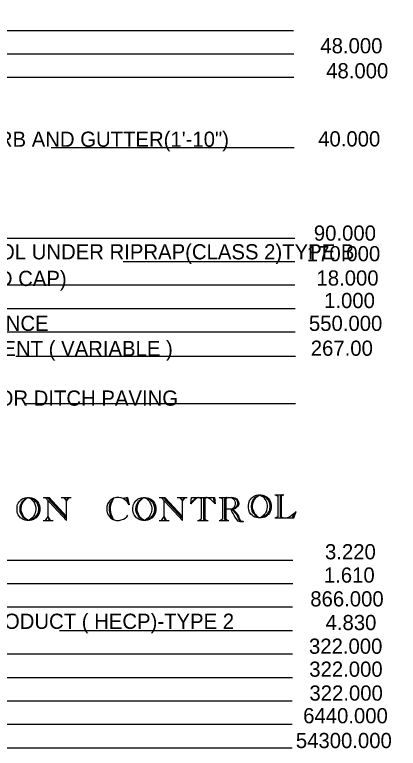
# Model space of a CAD drawing. Extents: x -13615 to 47191, y -1934 to 4415.
# Drawn here: x -11541 to -11338.5, y 1111.4 to 1498.5 of the extents above; entities that cross this region are included whole.
import ezdxf

# ---------------------------------------------------------------- set-up
doc = ezdxf.new("R2010")
doc.units = 0
doc.layers.add('Default', color=7, linetype='Continuous')

msp = doc.modelspace()

# ---------------------------------------------------------------- linework, layer by layer
at = {"layer": 'Default'}
for p, q in [((-11654.4, 1490.25), (-11428.18, 1490.25)), ((-11428.18, 1490.25), (-11419.65, 1490.25)), ((-11419.65, 1490.25), (-11407.18, 1490.25)), ((-11407.18, 1490.25), (-11399.27, 1490.25)), ((-11399.27, 1490.25), (-11393.78, 1490.25)), ((-11649.58, 1477.88), (-11428.19, 1477.88)), ((-11428.19, 1477.88), (-11420.03, 1477.88)), ((-11420.03, 1477.88), (-11406.95, 1477.88)), ((-11406.95, 1477.88), (-11399.14, 1477.88)), ((-11399.14, 1477.88), (-11393.71, 1477.88)), ((-11650.51, 1465.5), (-11428.21, 1465.5)), ((-11428.21, 1465.5), (-11420.41, 1465.5)), ((-11420.41, 1465.5), (-11406.71, 1465.5)), ((-11406.71, 1465.5), (-11399.02, 1465.5)), ((-11399.02, 1465.5), (-11393.64, 1465.5)), ((-11521.75, 1428.38), (-11428.26, 1428.38)), ((-11428.26, 1428.38), (-11421.56, 1428.38)), ((-11421.56, 1428.38), (-11406.01, 1428.38)), ((-11406.01, 1428.38), (-11398.64, 1428.38)), ((-11398.64, 1428.38), (-11393.42, 1428.38)), ((-11667.77, 1380.65), (-11428.31, 1380.65)), ((-11428.31, 1380.65), (-11422.71, 1380.65)), ((-11422.71, 1380.65), (-11415.63, 1380.65)), ((-11415.63, 1380.65), (-11405.31, 1380.65)), ((-11405.31, 1380.65), (-11398.25, 1380.65)), ((-11398.25, 1380.65), (-11393.19, 1380.65)), ((-11483.68, 1368.27), (-11428.33, 1368.27)), ((-11428.33, 1368.27), (-11423.09, 1368.27)), ((-11423.09, 1368.27), (-11417.44, 1368.27)), ((-11417.44, 1368.27), (-11405.08, 1368.27)), ((-11405.08, 1368.27), (-11398.13, 1368.27)), ((-11398.13, 1368.27), (-11393.12, 1368.27)), ((-11576.84, 1355.9), (-11428.35, 1355.9)), ((-11428.35, 1355.9), (-11423.47, 1355.9)), ((-11423.47, 1355.9), (-11419.24, 1355.9)), ((-11419.24, 1355.9), (-11404.84, 1355.9)), ((-11404.84, 1355.9), (-11398, 1355.9)), ((-11398, 1355.9), (-11393.05, 1355.9)), ((-11659.64, 1343.52), (-11428.37, 1343.52)), ((-11428.37, 1343.52), (-11423.86, 1343.52)), ((-11423.86, 1343.52), (-11421.05, 1343.52)), ((-11421.05, 1343.52), (-11404.61, 1343.52)), ((-11404.61, 1343.52), (-11397.87, 1343.52)), ((-11397.87, 1343.52), (-11392.97, 1343.52)), ((-11586.13, 1331.15), (-11428.38, 1331.15)), ((-11428.38, 1331.15), (-11424.24, 1331.15)), ((-11424.24, 1331.15), (-11422.85, 1331.15)), ((-11422.85, 1331.15), (-11404.37, 1331.15)), ((-11404.37, 1331.15), (-11397.75, 1331.15)), ((-11397.75, 1331.15), (-11392.9, 1331.15)), ((-11540.39, 1318.37), (-11392.79, 1318.37)), ((-11536.07, 1293.34), (-11392.79, 1293.34)), ((-11658.4, 1210.74), (-11394.23, 1210.74)), ((-11658.4, 1198.37), (-11394.28, 1198.37)), ((-11693.42, 1185.99), (-11394.32, 1185.99)), ((-11517.36, 1173.62), (-11394.36, 1173.62)), ((-11642.48, 1161.24), (-11394.4, 1161.24)), ((-11612.41, 1148.87), (-11394.44, 1148.87)), ((-11652.03, 1136.49), (-11394.48, 1136.49)), ((-11612.41, 1124.12), (-11394.53, 1124.12)), ((-11654.15, 1111.74), (-11394.57, 1111.74))]:
    msp.add_line(p, q, dxfattribs=at)
for points in [[(-11537.28, 1232.6), (-11537.91, 1233.08), (-11538.55, 1233.71), (-11539.18, 1234.65), (-11539.33, 1234.97), (-11539.49, 1235.44), (-11539.65, 1235.92), (-11539.81, 1237.02), (-11539.81, 1238.28), (-11539.65, 1239.39), (-11539.49, 1240.02), (-11539.18, 1240.81), (-11538.7, 1241.44), (-11538.23, 1242.07), (-11537.91, 1242.39), (-11537.28, 1242.86), (-11536.81, 1243.17), (-11536.02, 1243.49), (-11535.55, 1243.65), (-11534.44, 1243.81), (-11533.81, 1243.81), (-11532.71, 1243.65), (-11532.23, 1243.49), (-11531.45, 1243.17), (-11530.97, 1242.86), (-11530.5, 1242.54), (-11529.71, 1241.75), (-11529.08, 1240.97), (-11528.76, 1240.49), (-11528.61, 1240.18), (-11528.45, 1239.7), (-11528.29, 1239.07), (-11528.13, 1238.13), (-11528.13, 1237.65), (-11528.29, 1236.39), (-11528.45, 1235.76), (-11528.61, 1235.44), (-11528.76, 1234.97), (-11529.08, 1234.5), (-11529.39, 1234.02), (-11530.03, 1233.39), (-11530.5, 1232.92), (-11530.97, 1232.6), (-11531.76, 1232.13), (-11532.23, 1231.97), (-11532.71, 1231.81), (-11533.81, 1231.66), (-11534.29, 1231.81), (-11534.6, 1231.97), (-11535.23, 1232.29), (-11535.86, 1232.76), (-11536.49, 1233.39), (-11537.13, 1234.18), (-11537.44, 1234.65), (-11537.76, 1235.29), (-11538.07, 1236.23), (-11538.23, 1237.34), (-11538.23, 1237.97), (-11538.07, 1239.07), (-11537.91, 1239.7), (-11537.76, 1240.18), (-11537.6, 1240.49), (-11537.44, 1240.81), (-11536.81, 1241.75), (-11536.18, 1242.39), (-11535.86, 1242.7), (-11535.39, 1243.02), (-11534.92, 1243.33), (-11534.6, 1243.49), (-11533.81, 1243.81), (-11532.55, 1243.49), (-11532.08, 1243.33), (-11531.76, 1243.17), (-11531.29, 1242.86), (-11530.81, 1242.54)], [(-11530.81, 1242.54), (-11530.34, 1242.07), (-11529.87, 1241.6), (-11529.55, 1241.28), (-11529.39, 1240.97), (-11528.92, 1240.02), (-11528.61, 1239.07), (-11528.45, 1238.13), (-11528.45, 1237.49), (-11528.61, 1236.39), (-11528.76, 1235.76), (-11529.08, 1234.97), (-11529.39, 1234.5), (-11529.71, 1234.02), (-11530.81, 1232.92), (-11531.45, 1232.45), (-11532.08, 1232.13), (-11532.55, 1231.97), (-11533.81, 1231.66), (-11534.76, 1232.13), (-11535.39, 1232.6), (-11536.18, 1233.23), (-11536.81, 1234.02), (-11537.28, 1234.97), (-11537.76, 1236.23), (-11537.91, 1237.34), (-11537.91, 1237.97), (-11537.76, 1239.23), (-11537.6, 1239.7), (-11537.28, 1240.49), (-11536.97, 1241.12), (-11536.65, 1241.6), (-11535.86, 1242.54), (-11535.23, 1243.02), (-11534.76, 1243.33), (-11533.81, 1243.81), (-11533.5, 1243.65), (-11532.71, 1243.17), (-11532.08, 1242.7), (-11531.76, 1242.39), (-11531.13, 1241.6), (-11530.66, 1240.81), (-11530.34, 1240.18), (-11530.03, 1239.23), (-11529.87, 1238.28), (-11529.87, 1237.49), (-11530.03, 1236.39), (-11530.18, 1235.76), (-11530.34, 1235.29), (-11530.66, 1234.65), (-11530.97, 1234.02), (-11531.45, 1233.39), (-11531.92, 1232.92), (-11532.71, 1232.29), (-11533.18, 1231.97), (-11533.81, 1231.66), (-11534.6, 1232.13), (-11535.07, 1232.45), (-11535.55, 1232.92), (-11536.18, 1233.55), (-11536.49, 1234.02), (-11536.97, 1234.97), (-11537.44, 1236.23), (-11537.6, 1237.34), (-11537.6, 1237.97), (-11537.44, 1239.23), (-11537.28, 1239.86), (-11536.97, 1240.65), (-11536.81, 1240.97), (-11536.49, 1241.44), (-11536.18, 1241.91), (-11535.71, 1242.39), (-11535.39, 1242.7), (-11534.6, 1243.33), (-11533.81, 1243.81), (-11533.18, 1243.81), (-11532.23, 1243.65), (-11531.6, 1243.49), (-11530.66, 1243.02), (-11529.87, 1242.54), (-11529.24, 1241.91), (-11528.76, 1241.28), (-11528.45, 1240.81), (-11528.13, 1240.02), (-11527.97, 1239.55), (-11527.82, 1238.28), (-11527.82, 1237.02), (-11527.97, 1235.92), (-11528.13, 1235.44), (-11528.29, 1234.97), (-11528.76, 1234.18), (-11529.08, 1233.71), (-11529.71, 1233.08), (-11530.34, 1232.6), (-11531.13, 1232.13), (-11532.08, 1231.81), (-11533.02, 1231.66), (-11534.6, 1231.66), (-11535.55, 1231.81), (-11536.49, 1232.13), (-11537.28, 1232.6)], [(-11525.92, 1243.81), (-11522.92, 1243.81), (-11513.62, 1233.71)], [(-11524.98, 1243.81), (-11513.62, 1231.66), (-11513.62, 1241.75), (-11512.2, 1243.81)], [(-11523.87, 1243.81), (-11513.62, 1232.76)], [(-11523.4, 1243.81), (-11513.62, 1233.39)], [(-11516.46, 1243.81), (-11511.25, 1243.81)], [(-11515.04, 1243.81), (-11513.62, 1241.75), (-11512.98, 1243.81)], [(-11513.62, 1241.75), (-11512.67, 1243.81)], [(-11483.79, 1243.17), (-11481.43, 1243.81), (-11480.64, 1239.86), (-11481.74, 1241.6), (-11482.37, 1242.23), (-11483.79, 1243.17), (-11484.9, 1243.65), (-11486, 1243.81), (-11487.26, 1243.81), (-11488.05, 1243.65), (-11488.84, 1243.33), (-11489.95, 1242.7), (-11490.42, 1242.39), (-11491.05, 1241.75), (-11491.84, 1240.65), (-11492.47, 1239.07), (-11492.47, 1236.71), (-11492, 1235.13), (-11491.05, 1233.71), (-11490.42, 1233.08), (-11489, 1232.13), (-11488.05, 1231.81), (-11487.26, 1231.66), (-11485.84, 1231.66), (-11484.74, 1231.97), (-11483.64, 1232.29), (-11482.69, 1232.92), (-11481.9, 1233.55), (-11481.27, 1234.5)], [(-11488.84, 1243.33), (-11489.79, 1241.44), (-11490.26, 1240.18), (-11490.58, 1238.6), (-11490.58, 1237.02), (-11490.26, 1235.13), (-11489.95, 1234.5), (-11489.32, 1233.08), (-11489.16, 1232.76), (-11488.53, 1231.97), (-11489.47, 1232.92), (-11490.11, 1234.02), (-11490.58, 1235.13), (-11490.89, 1236.71), (-11490.89, 1238.44), (-11490.58, 1240.02), (-11490.26, 1240.81), (-11489.79, 1241.91), (-11488.84, 1243.33), (-11489.47, 1242.54), (-11489.95, 1241.91), (-11490.26, 1241.28), (-11490.74, 1240.65), (-11491.21, 1239.07), (-11491.21, 1236.71), (-11490.58, 1234.65), (-11490.42, 1234.18), (-11490.11, 1233.55), (-11489.63, 1232.92), (-11489.32, 1232.6), (-11488.68, 1232.13)], [(-11480.64, 1239.86), (-11481.43, 1243.81), (-11483.79, 1243.17)], [(-11482.06, 1243.65), (-11481.74, 1241.6)], [(-11481.74, 1243.65), (-11481.27, 1240.81)], [(-11476.06, 1232.6), (-11476.69, 1233.08), (-11477.32, 1233.71), (-11477.96, 1234.65), (-11478.11, 1234.97), (-11478.27, 1235.44), (-11478.43, 1235.92), (-11478.59, 1237.02), (-11478.59, 1238.28), (-11478.43, 1239.39), (-11478.27, 1240.02), (-11477.96, 1240.81), (-11477.48, 1241.44), (-11477.01, 1242.07), (-11476.69, 1242.39), (-11476.06, 1242.86), (-11475.59, 1243.17), (-11474.8, 1243.49), (-11474.33, 1243.65), (-11473.22, 1243.81), (-11472.59, 1243.81), (-11471.49, 1243.65), (-11471.01, 1243.49), (-11470.22, 1243.17), (-11469.75, 1242.86), (-11469.28, 1242.54), (-11468.49, 1241.75), (-11467.86, 1240.97), (-11467.54, 1240.49), (-11467.38, 1240.18), (-11467.23, 1239.7), (-11467.07, 1239.07), (-11466.91, 1238.13), (-11466.91, 1237.65), (-11467.07, 1236.39), (-11467.23, 1235.76), (-11467.38, 1235.44), (-11467.54, 1234.97), (-11467.86, 1234.5), (-11468.17, 1234.02), (-11468.8, 1233.39), (-11469.28, 1232.92), (-11469.75, 1232.6), (-11470.54, 1232.13), (-11471.01, 1231.97), (-11471.49, 1231.81), (-11472.59, 1231.66), (-11473.06, 1231.81), (-11473.38, 1231.97), (-11474.01, 1232.29), (-11474.64, 1232.76), (-11475.27, 1233.39), (-11475.9, 1234.18), (-11476.22, 1234.65), (-11476.54, 1235.29), (-11476.85, 1236.23), (-11477.01, 1237.34), (-11477.01, 1237.97), (-11476.85, 1239.07), (-11476.69, 1239.7), (-11476.54, 1240.18), (-11476.38, 1240.49), (-11476.22, 1240.81), (-11475.59, 1241.75), (-11474.96, 1242.39), (-11474.64, 1242.7), (-11474.17, 1243.02), (-11473.7, 1243.33), (-11473.38, 1243.49), (-11472.59, 1243.81), (-11471.33, 1243.49), (-11470.85, 1243.33), (-11470.54, 1243.17), (-11470.07, 1242.86), (-11469.59, 1242.54)], [(-11469.59, 1242.54), (-11469.12, 1242.07), (-11468.65, 1241.6), (-11468.33, 1241.28), (-11468.17, 1240.97), (-11467.7, 1240.02), (-11467.38, 1239.07), (-11467.23, 1238.13), (-11467.23, 1237.49), (-11467.38, 1236.39), (-11467.54, 1235.76), (-11467.86, 1234.97), (-11468.17, 1234.5), (-11468.49, 1234.02), (-11469.59, 1232.92), (-11470.22, 1232.45), (-11470.85, 1232.13), (-11471.33, 1231.97), (-11472.59, 1231.66), (-11473.54, 1232.13), (-11474.17, 1232.6), (-11474.96, 1233.23), (-11475.59, 1234.02), (-11476.06, 1234.97), (-11476.54, 1236.23), (-11476.69, 1237.34), (-11476.69, 1237.97), (-11476.54, 1239.23), (-11476.38, 1239.7), (-11476.06, 1240.49), (-11475.75, 1241.12), (-11475.43, 1241.6), (-11474.64, 1242.54), (-11474.01, 1243.02), (-11473.54, 1243.33), (-11472.59, 1243.81), (-11472.28, 1243.65), (-11471.49, 1243.17), (-11470.85, 1242.7), (-11470.54, 1242.39), (-11469.91, 1241.6), (-11469.43, 1240.81), (-11469.12, 1240.18), (-11468.8, 1239.23), (-11468.65, 1238.28), (-11468.65, 1237.49), (-11468.8, 1236.39), (-11468.96, 1235.76), (-11469.12, 1235.29), (-11469.43, 1234.65), (-11469.75, 1234.02), (-11470.22, 1233.39), (-11470.7, 1232.92), (-11471.49, 1232.29), (-11471.96, 1231.97), (-11472.59, 1231.66), (-11473.38, 1232.13), (-11473.85, 1232.45), (-11474.33, 1232.92), (-11474.96, 1233.55), (-11475.27, 1234.02), (-11475.75, 1234.97), (-11476.22, 1236.23), (-11476.38, 1237.34), (-11476.38, 1237.97), (-11476.22, 1239.23), (-11476.06, 1239.86), (-11475.75, 1240.65), (-11475.59, 1240.97), (-11475.27, 1241.44), (-11474.96, 1241.91), (-11474.48, 1242.39), (-11474.17, 1242.7), (-11473.38, 1243.33), (-11472.59, 1243.81), (-11471.96, 1243.81), (-11471.01, 1243.65), (-11470.38, 1243.49), (-11469.43, 1243.02), (-11468.65, 1242.54), (-11468.01, 1241.91), (-11467.54, 1241.28), (-11467.23, 1240.81), (-11466.91, 1240.02), (-11466.75, 1239.55), (-11466.59, 1238.28), (-11466.59, 1237.02), (-11466.75, 1235.92), (-11466.91, 1235.44), (-11467.07, 1234.97), (-11467.54, 1234.18), (-11467.86, 1233.71), (-11468.49, 1233.08), (-11469.12, 1232.6), (-11469.91, 1232.13), (-11470.85, 1231.81), (-11471.8, 1231.66), (-11473.38, 1231.66), (-11474.33, 1231.81), (-11475.27, 1232.13), (-11476.06, 1232.6)], [(-11464.7, 1243.81), (-11461.7, 1243.81), (-11452.39, 1233.71)], [(-11463.75, 1243.81), (-11452.39, 1231.66), (-11452.39, 1241.75), (-11450.97, 1243.81)], [(-11462.65, 1243.81), (-11452.39, 1232.76)], [(-11462.18, 1243.81), (-11452.39, 1233.39)], [(-11455.23, 1243.81), (-11450.03, 1243.81)], [(-11453.81, 1243.81), (-11452.39, 1241.75), (-11451.76, 1243.81)], [(-11452.39, 1241.75), (-11451.45, 1243.81)], [(-11444.03, 1243.81), (-11444.5, 1243.65), (-11444.82, 1243.33), (-11445.77, 1242.7), (-11447.98, 1240.49), (-11447.66, 1243.81), (-11435.51, 1243.81), (-11435.19, 1240.49), (-11435.67, 1240.97), (-11437.56, 1242.7), (-11439.3, 1243.81)], [(-11444.35, 1243.81), (-11445.29, 1243.17), (-11445.77, 1242.86), (-11446.24, 1242.39), (-11447.03, 1241.6), (-11447.5, 1241.12), (-11447.98, 1240.49), (-11447.66, 1241.12), (-11447.19, 1241.6), (-11446.71, 1242.39), (-11445.92, 1243.02), (-11445.45, 1243.49), (-11444.66, 1243.81)], [(-11443.72, 1243.81), (-11442.61, 1243.17), (-11442.61, 1232.29), (-11443.72, 1231.66)], [(-11440.24, 1243.81), (-11441.35, 1243.17), (-11441.35, 1232.29), (-11440.24, 1231.66)], [(-11439.93, 1243.81), (-11441.03, 1243.17), (-11441.03, 1232.29), (-11439.93, 1231.66)], [(-11439.61, 1243.81), (-11440.72, 1243.17), (-11440.72, 1232.29), (-11439.61, 1231.66)], [(-11436.14, 1243.81), (-11435.83, 1241.12)], [(-11435.83, 1243.81), (-11435.51, 1240.81)], [(-11433.14, 1243.81), (-11425.73, 1243.81), (-11425.1, 1243.65), (-11423.83, 1243.02), (-11423.05, 1241.91), (-11422.73, 1240.81), (-11422.73, 1240.18), (-11423.2, 1239.07), (-11423.68, 1238.6), (-11424.47, 1237.97), (-11425.57, 1237.65), (-11425.73, 1237.65), (-11424.62, 1237.97), (-11424.31, 1238.13), (-11423.68, 1238.91), (-11423.05, 1240.33), (-11423.05, 1241.12), (-11423.52, 1242.23), (-11423.83, 1242.7), (-11424.31, 1243.17), (-11425.1, 1243.49), (-11425.57, 1243.65), (-11426.36, 1243.81), (-11425.73, 1243.65), (-11425.25, 1243.49), (-11424.78, 1243.17), (-11424.31, 1242.86), (-11423.83, 1242.39), (-11423.52, 1241.6), (-11423.36, 1241.12), (-11423.36, 1240.33), (-11423.68, 1239.23), (-11424.78, 1238.13), (-11425.25, 1237.81), (-11425.73, 1237.65), (-11429.51, 1237.65)], [(-11432.51, 1243.81), (-11431.41, 1243.02), (-11431.41, 1232.29), (-11432.51, 1231.66)], [(-11429.2, 1243.81), (-11430.3, 1243.02), (-11430.3, 1232.29), (-11429.2, 1231.66)], [(-11428.88, 1243.81), (-11429.83, 1243.02), (-11429.83, 1232.29), (-11428.88, 1231.66)], [(-11428.41, 1243.81), (-11429.51, 1243.02), (-11429.51, 1232.29), (-11428.41, 1231.66)], [(-11426.36, 1243.81), (-11425.41, 1242.86), (-11424.78, 1241.75), (-11424.62, 1241.12), (-11424.62, 1240.33), (-11424.78, 1239.55), (-11425.41, 1238.28), (-11426.36, 1237.65), (-11425.73, 1237.18), (-11424.94, 1236.71), (-11423.99, 1235.76), (-11423.68, 1235.29), (-11423.52, 1234.97), (-11423.2, 1234.5), (-11422.89, 1233.87), (-11422.73, 1233.39), (-11422.57, 1232.76), (-11422.26, 1232.29), (-11422.1, 1231.97), (-11421.63, 1231.5), (-11421.15, 1231.34), (-11420.84, 1231.18), (-11420.21, 1231.18), (-11420.84, 1230.87), (-11421.94, 1230.87), (-11422.57, 1231.03), (-11423.05, 1231.34), (-11423.68, 1232.13), (-11424.62, 1233.39), (-11425.25, 1234.18), (-11425.73, 1235.29), (-11426.2, 1236.07), (-11426.52, 1236.86), (-11426.83, 1237.65)], [(-11415.11, 1233.93), (-11415.74, 1234.4), (-11416.38, 1235.03), (-11417.01, 1235.98), (-11417.16, 1236.3), (-11417.32, 1236.77), (-11417.48, 1237.24), (-11417.64, 1238.35), (-11417.64, 1239.61), (-11417.48, 1240.71), (-11417.32, 1241.34), (-11417.01, 1242.13), (-11416.53, 1242.76), (-11416.06, 1243.4), (-11415.74, 1243.71), (-11415.11, 1244.18), (-11414.64, 1244.5), (-11413.85, 1244.82), (-11413.38, 1244.97), (-11412.27, 1245.13), (-11411.64, 1245.13), (-11410.54, 1244.97), (-11410.06, 1244.82), (-11409.28, 1244.5), (-11408.8, 1244.18), (-11408.33, 1243.87), (-11407.54, 1243.08), (-11406.91, 1242.29), (-11406.59, 1241.82), (-11406.44, 1241.5), (-11406.28, 1241.03), (-11406.12, 1240.4), (-11405.96, 1239.45), (-11405.96, 1238.98), (-11406.12, 1237.72), (-11406.28, 1237.08), (-11406.44, 1236.77), (-11406.59, 1236.3), (-11406.91, 1235.82), (-11407.22, 1235.35), (-11407.86, 1234.72), (-11408.33, 1234.24), (-11408.8, 1233.93), (-11409.59, 1233.46), (-11410.06, 1233.3), (-11410.54, 1233.14), (-11411.64, 1232.98), (-11412.12, 1233.14), (-11412.43, 1233.3), (-11413.06, 1233.61), (-11413.69, 1234.09), (-11414.32, 1234.72), (-11414.96, 1235.51), (-11415.27, 1235.98), (-11415.59, 1236.61), (-11415.9, 1237.56), (-11416.06, 1238.66), (-11416.06, 1239.29), (-11415.9, 1240.4), (-11415.74, 1241.03), (-11415.59, 1241.5), (-11415.43, 1241.82), (-11415.27, 1242.13), (-11414.64, 1243.08), (-11414.01, 1243.71), (-11413.69, 1244.03), (-11413.22, 1244.34), (-11412.75, 1244.66), (-11412.43, 1244.82), (-11411.64, 1245.13), (-11410.38, 1244.82), (-11409.91, 1244.66), (-11409.59, 1244.5), (-11409.12, 1244.18), (-11408.64, 1243.87)], [(-11408.64, 1243.87), (-11408.17, 1243.4), (-11407.7, 1242.92), (-11407.38, 1242.61), (-11407.22, 1242.29), (-11406.75, 1241.34), (-11406.44, 1240.4), (-11406.28, 1239.45), (-11406.28, 1238.82), (-11406.44, 1237.72), (-11406.59, 1237.08), (-11406.91, 1236.3), (-11407.22, 1235.82), (-11407.54, 1235.35), (-11408.64, 1234.24), (-11409.28, 1233.77), (-11409.91, 1233.46), (-11410.38, 1233.3), (-11411.64, 1232.98), (-11412.59, 1233.46), (-11413.22, 1233.93), (-11414.01, 1234.56), (-11414.64, 1235.35), (-11415.11, 1236.3), (-11415.59, 1237.56), (-11415.74, 1238.66), (-11415.74, 1239.29), (-11415.59, 1240.56), (-11415.43, 1241.03), (-11415.11, 1241.82), (-11414.8, 1242.45), (-11414.48, 1242.92), (-11413.69, 1243.87), (-11413.06, 1244.34), (-11412.59, 1244.66), (-11411.64, 1245.13), (-11411.33, 1244.97), (-11410.54, 1244.5), (-11409.91, 1244.03), (-11409.59, 1243.71), (-11408.96, 1242.92), (-11408.49, 1242.13), (-11408.17, 1241.5), (-11407.86, 1240.56), (-11407.7, 1239.61), (-11407.7, 1238.82), (-11407.86, 1237.72), (-11408.01, 1237.08), (-11408.17, 1236.61), (-11408.49, 1235.98), (-11408.8, 1235.35), (-11409.28, 1234.72), (-11409.75, 1234.24), (-11410.54, 1233.61), (-11411.01, 1233.3), (-11411.64, 1232.98), (-11412.43, 1233.46), (-11412.9, 1233.77), (-11413.38, 1234.24), (-11414.01, 1234.88), (-11414.32, 1235.35), (-11414.8, 1236.3), (-11415.27, 1237.56), (-11415.43, 1238.66), (-11415.43, 1239.29), (-11415.27, 1240.56), (-11415.11, 1241.19), (-11414.8, 1241.98), (-11414.64, 1242.29), (-11414.32, 1242.76), (-11414.01, 1243.24), (-11413.54, 1243.71), (-11413.22, 1244.03), (-11412.43, 1244.66), (-11411.64, 1245.13), (-11411.01, 1245.13), (-11410.06, 1244.97), (-11409.43, 1244.82), (-11408.49, 1244.34), (-11407.7, 1243.87), (-11407.07, 1243.24), (-11406.59, 1242.61), (-11406.28, 1242.13), (-11405.96, 1241.34), (-11405.8, 1240.87), (-11405.65, 1239.61), (-11405.65, 1238.35), (-11405.8, 1237.24), (-11405.96, 1236.77), (-11406.12, 1236.3), (-11406.59, 1235.51), (-11406.91, 1235.03), (-11407.54, 1234.4), (-11408.17, 1233.93), (-11408.96, 1233.46), (-11409.91, 1233.14), (-11410.85, 1232.98), (-11412.43, 1232.98), (-11413.38, 1233.14), (-11414.32, 1233.46), (-11415.11, 1233.93)], [(-11403.75, 1245.13), (-11398.86, 1245.13)], [(-11403.28, 1245.13), (-11402.18, 1244.5), (-11402.18, 1233.61), (-11403.28, 1232.98)], [(-11399.97, 1245.13), (-11400.91, 1244.5), (-11400.91, 1233.61), (-11399.97, 1232.98)], [(-11399.49, 1245.13), (-11400.6, 1244.5), (-11400.6, 1233.61), (-11399.49, 1232.98)], [(-11399.18, 1245.13), (-11400.28, 1244.5), (-11400.28, 1233.61), (-11399.18, 1232.98)], [(-11523.56, 1242.23), (-11523.56, 1233.71), (-11524.98, 1231.66)], [(-11462.33, 1242.23), (-11462.33, 1233.71), (-11463.75, 1231.66)], [(-11426.52, 1237.65), (-11426.04, 1237.34), (-11425.57, 1237.02), (-11424.31, 1235.76), (-11423.83, 1235.13), (-11423.36, 1234.34), (-11423.05, 1233.71), (-11422.89, 1233.08), (-11422.57, 1232.29), (-11421.94, 1231.66), (-11420.99, 1231.18), (-11420.52, 1231.03), (-11421.15, 1231.18), (-11421.31, 1231.18), (-11422.1, 1231.66), (-11422.57, 1232.13), (-11422.89, 1232.6), (-11423.05, 1233.23), (-11423.2, 1233.55), (-11423.52, 1234.34), (-11423.99, 1234.97), (-11424.31, 1235.44), (-11424.62, 1235.76), (-11424.94, 1236.23), (-11425.41, 1236.71), (-11425.73, 1236.86), (-11426.04, 1237.18), (-11426.36, 1237.34), (-11426.67, 1237.65)], [(-11403.75, 1232.98), (-11393.65, 1232.98), (-11392.39, 1236.45), (-11394.13, 1234.72), (-11395.07, 1234.09), (-11396.02, 1233.46), (-11396.65, 1233.14), (-11397.13, 1232.98)], [(-11394.44, 1232.98), (-11393.65, 1235.19)], [(-11393.02, 1235.82), (-11394.13, 1232.98)], [(-11525.92, 1231.66), (-11520.72, 1231.66)], [(-11523.56, 1233.71), (-11522.92, 1231.66)], [(-11522.61, 1231.66), (-11523.56, 1233.71), (-11522.29, 1231.66)], [(-11464.7, 1231.66), (-11459.49, 1231.66)], [(-11462.33, 1233.71), (-11461.7, 1231.66)], [(-11461.39, 1231.66), (-11462.33, 1233.71), (-11461.07, 1231.66)], [(-11444.5, 1231.66), (-11438.82, 1231.66)], [(-11433.14, 1231.66), (-11427.94, 1231.66)]]:
    msp.add_lwpolyline(points, dxfattribs=at)

# ---------------------------------------------------------------- texts
for s, height, p in [('MAINTENANCE STONE                                                                                                                                            50.000     ', 8.01562, (-11735.47, 1490.39)), ('48.000', 8.016, (-11379.66, 1478.14)), (' 48.000', 8.016, (-11379.57, 1464.93)), ('BRIDGE APPROACH CONCRETE CURB AND GUTTER(1\'-10")', 8.0156, (-11735.72, 1428.8)), ('40.000', 8.016, (-11380.82, 1429)), (' 90.000', 8.016, (-11386.07, 1379.28)), ('GEOTEXTILE FOR EROSION CONTROL UNDER RIPRAP(CLASS 2)TYPE B', 8.0156, (-11735.72, 1369.41)), (' 170.000', 8.016, (-11389.78, 1368.42)), ('RIGHT OF WAY MARKER(REBAR AND CAP)', 8.0156, (-11735.72, 1355.36)), ('18.000', 8.016, (-11381.7, 1355.58)), ('1.000', 8.016, (-11377.68, 1343.69)), ('STABILIZED CONSTRUCTION ENTRANCE', 8.0156, (-11735.72, 1331.66)), ('550.000', 8.016, (-11385.7, 1331.66)), ('MILLING EXISTING ASPHALT PAVEMENT ( VARIABLE )', 8.0156, (-11735.72, 1318.37)), ('267.00', 8.016, (-11384.72, 1318.53)), ('HOT MIX  ASPH. CONC. SURF. CR. FOR DITCH PAVING                                                                                     5.000             TON', 8.01562, (-11736.45, 1292.21)), ('3.220', 8.016, (-11377.21, 1211.14)), ('1.610', 8.016, (-11377.8, 1198.84)), ('866.000', 8.016, (-11384.99, 1186.28)), ('HYDRAULIC EROSION CONTROL PRODUCT ( HECP)-TYPE 2', 8.0156, (-11734.31, 1174.45)), ('4.830', 8.016, (-11376.91, 1173.79)), ('322.000', 8.016, (-11385.66, 1161.3)), ('322.000', 8.016, (-11385.52, 1149.18)), ('322.000', 8.016, (-11385.42, 1136.58)), ('6440.000', 8.016, (-11388.74, 1124.63)), ('54300.000', 8.016, (-11392.6, 1111.53))]:
    msp.add_text(s, height=height, dxfattribs=at).set_placement(p)

doc.saveas('drawing.dxf')
